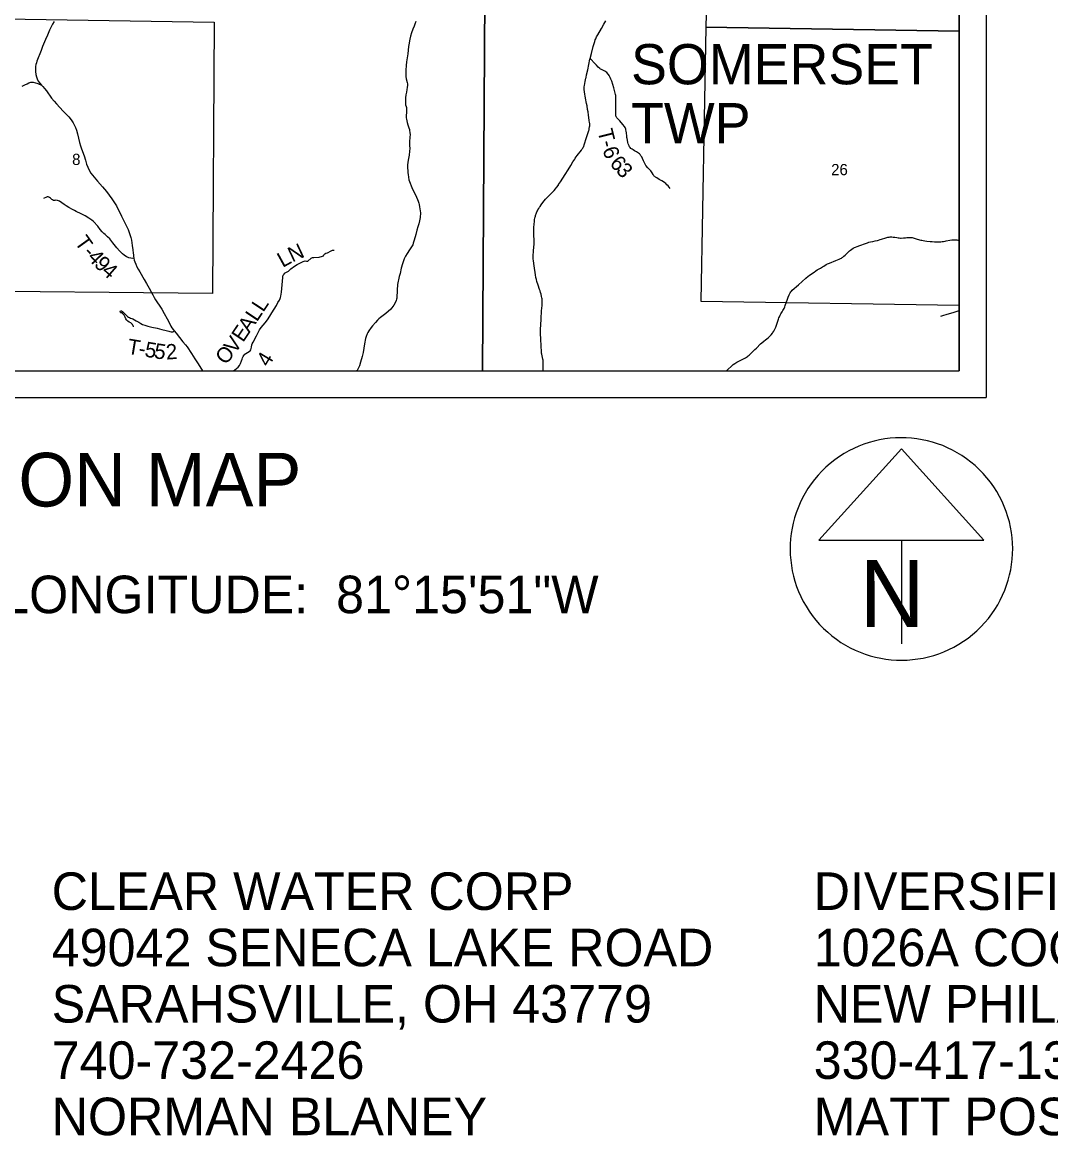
# Model space of a CAD drawing. Extents: x 0 to 34, y 0 to 22.
# Drawn here: x 5.408 to 9.241, y 11.247 to 15.399 of the extents above; entities that cross this region are included whole.
import ezdxf

# ---------------------------------------------------------------- set-up
doc = ezdxf.new("R2010")
doc.units = 0
for name, color, linetype in [('GM_X_Corporation', 7, 'Continuous'), ('GM_X_County_Road', 7, 'Continuous'), ('GM_X_Section_Text', 7, 'Continuous'), ('GM_X_State_Route', 7, 'Continuous'), ('GM_X_Township_Road', 7, 'Continuous'), ('GM_X_Township_Road_Text', 7, 'Continuous'), ('GM_X_Township_Text', 7, 'Continuous'), ('SH_Data', 7, 'Continuous'), ('SH_Text', 7, 'Continuous')]:
    doc.layers.add(name, color=color, linetype=linetype)

msp = doc.modelspace()

# ---------------------------------------------------------------- linework, layer by layer
at = {"layer": 'GM_X_Corporation'}
for points in [[(7.1227, 14.1), (8.9, 14.1), (8.9, 20.9), (7.231, 20.9), (7.2244, 20.2649), (7.1982, 19.2496), (7.1981, 19.2461), (7.1974, 19.2018), (7.1957, 19.0991), (7.1992, 18.9556), (7.197, 18.9465), (7.1949, 18.8464), (7.1846, 18.5133), (7.1817, 18.3306), (7.1804, 18.2238), (7.1572, 17.4131), (7.1504, 16.6562), (7.1434, 16.3848), (7.1318, 15.4937)], [(8.9, 15.3661), (8.9, 16.3711), (7.9815, 16.3875), (7.9552, 15.3809)], [(5.1041, 15.416), (6.1226, 15.3998), (6.117, 14.3875), (5.088, 14.3982)], [(8.9, 14.345), (8.9, 15.3661), (7.9552, 15.3809), (7.9363, 14.3597)]]:
    msp.add_lwpolyline(points, close=True, dxfattribs=at)
at = {"layer": 'GM_X_County_Road'}
for points in [[(5.5268, 15.402), (5.5206, 15.3924), (5.5162, 15.3845), (5.5087, 15.3693), (5.501, 15.3514), (5.4945, 15.3351), (5.4832, 15.3087), (5.4773, 15.2938), (5.4622, 15.254), (5.46, 15.2477), (5.4585, 15.2414), (5.4574, 15.2347), (5.4569, 15.2264), (5.4568, 15.2163), (5.4583, 15.2048), (5.4604, 15.1954), (5.4633, 15.1885), (5.4673, 15.1802), (5.4732, 15.1721), (5.4797, 15.1642)], [(5.4797, 15.1642), (5.4838, 15.1596), (5.4903, 15.1523), (5.4975, 15.1435), (5.5169, 15.1169), (5.5259, 15.1052), (5.5355, 15.0947), (5.5603, 15.0677), (5.5809, 15.0463), (5.5897, 15.0357), (5.5972, 15.0239), (5.6007, 15.0169), (5.6059, 15.0065), (5.6094, 14.9976), (5.6139, 14.9834), (5.6176, 14.9676), (5.6213, 14.9515), (5.6251, 14.9387), (5.6288, 14.9274), (5.6385, 14.9011), (5.643, 14.8854), (5.6469, 14.8708), (5.6513, 14.8594), (5.6574, 14.8476), (5.6636, 14.837), (5.669, 14.8293), (5.6882, 14.8064), (5.7064, 14.7855), (5.7216, 14.7682), (5.7312, 14.7551), (5.7414, 14.7406), (5.7535, 14.7229), (5.7582, 14.7148), (5.7641, 14.7037), (5.7723, 14.6876), (5.7771, 14.6762), (5.796, 14.6391), (5.8016, 14.627), (5.8045, 14.6197), (5.8087, 14.6074), (5.8117, 14.5967), (5.8141, 14.5871), (5.8174, 14.5673), (5.8197, 14.5504), (5.821, 14.538), (5.8218, 14.5316), (5.8223, 14.5274), (5.8232, 14.5197), (5.8246, 14.5125), (5.8265, 14.5061), (5.8302, 14.4968), (5.8347, 14.4877), (5.8398, 14.4783), (5.8453, 14.4685), (5.8618, 14.4398), (5.8703, 14.425), (5.8805, 14.408), (5.8885, 14.3942), (5.8943, 14.383), (5.8995, 14.3728), (5.9047, 14.3644), (5.9094, 14.357), (5.9197, 14.3413), (5.9275, 14.3291), (5.9361, 14.3132), (5.9472, 14.293), (5.9583, 14.2718), (5.9613, 14.2664), (5.9655, 14.26), (5.9699, 14.2538), (5.974, 14.2484), (5.9811, 14.2394), (5.9939, 14.2235), (6.0065, 14.2081), (6.0161, 14.1968), (6.0223, 14.1885), (6.038, 14.1646), (6.0512, 14.1441), (6.0631, 14.1254), (6.0798, 14.1)]]:
    msp.add_lwpolyline(points, dxfattribs=at)
at = {"layer": 'GM_X_State_Route'}
msp.add_lwpolyline([(7.3496, 14.1), (7.3491, 14.1043), (7.3488, 14.1094), (7.3487, 14.1117), (7.3494, 14.1306), (7.3492, 14.1357), (7.3488, 14.1398), (7.3482, 14.1433), (7.3442, 14.1611), (7.3434, 14.166), (7.343, 14.1697), (7.3415, 14.1936), (7.3403, 14.2158), (7.3393, 14.2397), (7.3394, 14.2562), (7.3399, 14.2704), (7.3414, 14.2938), (7.3433, 14.3236), (7.3452, 14.3437), (7.3457, 14.3519), (7.3458, 14.3563), (7.3456, 14.3635), (7.3451, 14.3677), (7.3444, 14.372), (7.3433, 14.3763), (7.3415, 14.3849), (7.3397, 14.3922), (7.3378, 14.3984), (7.3361, 14.4034), (7.3306, 14.4193), (7.3259, 14.4323), (7.3238, 14.4396), (7.3217, 14.4482), (7.3202, 14.4572), (7.3155, 14.4908), (7.3131, 14.5093), (7.3121, 14.5174), (7.3115, 14.5253), (7.3128, 14.5481), (7.3153, 14.5716), (7.3158, 14.5797), (7.3157, 14.5886), (7.3148, 14.604), (7.3145, 14.6136), (7.3149, 14.6337), (7.3156, 14.6464), (7.3164, 14.6569), (7.3172, 14.6632), (7.3184, 14.6695), (7.3191, 14.6724), (7.32, 14.6758), (7.3211, 14.6793), (7.3243, 14.6881), (7.3259, 14.6921), (7.328, 14.6965), (7.3297, 14.6998), (7.3326, 14.705), (7.3357, 14.7096), (7.3379, 14.7127), (7.3422, 14.7188), (7.3482, 14.7269), (7.358, 14.7391), (7.3637, 14.7453), (7.3853, 14.7674), (7.3896, 14.7721), (7.3951, 14.7786), (7.3988, 14.7832), (7.4057, 14.7924), (7.4066, 14.7938), (7.4137, 14.8042), (7.4314, 14.8316), (7.4422, 14.8492), (7.4521, 14.8655), (7.4599, 14.8784), (7.4669, 14.8893), (7.469, 14.8924), (7.4764, 14.9028), (7.4916, 14.9226), (7.4948, 14.927), (7.4968, 14.9301), (7.4986, 14.9333), (7.5002, 14.9365), (7.5023, 14.9421), (7.511, 14.9698), (7.519, 14.9952), (7.52, 14.9987), (7.5209, 15.0026), (7.5221, 15.0095), (7.5225, 15.0132), (7.5227, 15.0178), (7.5226, 15.0223), (7.5224, 15.0247), (7.521, 15.0347), (7.5184, 15.0525), (7.5164, 15.0652), (7.515, 15.0745), (7.5129, 15.0872), (7.511, 15.0968), (7.5071, 15.1166), (7.5057, 15.1249), (7.5047, 15.1302), (7.5029, 15.1415), (7.5023, 15.1475), (7.5022, 15.1531), (7.5025, 15.1588), (7.503, 15.163), (7.506, 15.1787), (7.5084, 15.1905), (7.5091, 15.1939), (7.511, 15.2028), (7.5153, 15.2225), (7.5236, 15.2612), (7.5243, 15.2644), (7.5287, 15.2829), (7.5358, 15.3091), (7.539, 15.3202), (7.5414, 15.328), (7.5435, 15.3337), (7.5452, 15.3378), (7.5485, 15.3448), (7.5526, 15.3526), (7.566, 15.3765), (7.5751, 15.392), (7.5828, 15.4043)], dxfattribs=at)
at = {"layer": 'GM_X_Township_Road'}
for points in [[(6.8744, 15.4024), (6.8712, 15.3925), (6.8684, 15.3854), (6.8635, 15.3737), (6.8585, 15.3599), (6.8547, 15.3476), (6.852, 15.3362), (6.8508, 15.3296), (6.8493, 15.3209), (6.8475, 15.3093), (6.8442, 15.2819), (6.8418, 15.2668), (6.8398, 15.2517), (6.8387, 15.2378), (6.8376, 15.2208), (6.8371, 15.2117), (6.8368, 15.2044), (6.8369, 15.1976), (6.8382, 15.1881), (6.8416, 15.1747), (6.843, 15.1692), (6.8432, 15.1643), (6.8424, 15.1564), (6.8411, 15.1487), (6.8393, 15.1384), (6.8376, 15.1285), (6.8363, 15.1173), (6.8356, 15.1097), (6.8355, 15.1053), (6.836, 15.0977), (6.8366, 15.0916), (6.8382, 15.0854), (6.8391, 15.081), (6.8396, 15.0769), (6.8398, 15.0711), (6.8398, 15.0655), (6.8382, 15.0488), (6.8386, 15.0426), (6.8392, 15.0382), (6.8404, 15.0324), (6.8424, 15.0255), (6.8451, 15.0171), (6.8489, 15.0052), (6.8505, 14.9999), (6.8515, 14.9952), (6.8525, 14.9877), (6.8528, 14.979), (6.8525, 14.9723), (6.8516, 14.9669), (6.8504, 14.9566), (6.8505, 14.9477), (6.8512, 14.9397), (6.8518, 14.9283), (6.8514, 14.9188), (6.8498, 14.9038), (6.8459, 14.8852), (6.8442, 14.8764), (6.8433, 14.8681), (6.8438, 14.8562), (6.8448, 14.8455), (6.8453, 14.8384), (6.8459, 14.8317), (6.8473, 14.8218), (6.8488, 14.8121), (6.8504, 14.8058), (6.8529, 14.7993), (6.8568, 14.7898), (6.8625, 14.7773), (6.8744, 14.7529), (6.883, 14.7323), (6.8853, 14.7253), (6.8865, 14.7192), (6.8877, 14.7111), (6.8914, 14.6883), (6.8905, 14.6719), (6.8886, 14.6592), (6.8853, 14.6471), (6.8815, 14.6362), (6.8786, 14.6239), (6.8745, 14.6082), (6.8689, 14.5874), (6.8649, 14.5752), (6.8629, 14.5698), (6.8588, 14.5623), (6.8509, 14.5509), (6.8418, 14.537), (6.8357, 14.5266), (6.8314, 14.5174), (6.8243, 14.4981), (6.8202, 14.4827), (6.8155, 14.4629), (6.812, 14.4513), (6.8064, 14.422), (6.8049, 14.3998), (6.8044, 14.3931), (6.8043, 14.3793), (6.8035, 14.3707), (6.8028, 14.367), (6.8013, 14.3619), (6.7974, 14.3528), (6.7921, 14.3438), (6.7816, 14.3297), (6.7622, 14.3133), (6.7433, 14.2989), (6.7368, 14.293), (6.7322, 14.2882), (6.7243, 14.2798), (6.7135, 14.2678), (6.7079, 14.2608), (6.6995, 14.249), (6.6956, 14.2427), (6.6926, 14.237), (6.6892, 14.2279), (6.6869, 14.2201), (6.6831, 14.1997), (6.6777, 14.1683), (6.6747, 14.1531), (6.6685, 14.1314), (6.6644, 14.1179), (6.6614, 14.1104), (6.6587, 14.1058), (6.6555, 14.1012), (6.6539, 14.1)], [(7.8225, 14.7799), (7.8147, 14.7892), (7.8105, 14.7936), (7.8063, 14.7975), (7.8027, 14.8004), (7.7973, 14.8043), (7.7921, 14.8075), (7.7819, 14.8132), (7.7724, 14.8189), (7.7679, 14.8218), (7.7651, 14.8237), (7.7633, 14.8253), (7.7617, 14.8271), (7.7607, 14.8288), (7.7596, 14.8314), (7.756, 14.8375), (7.7534, 14.8412), (7.7502, 14.8452), (7.7467, 14.8491), (7.7429, 14.8528), (7.7394, 14.8564), (7.732, 14.8652), (7.7301, 14.8682), (7.7288, 14.8706), (7.7253, 14.8774), (7.7227, 14.8832), (7.7192, 14.8917), (7.7165, 14.8975), (7.7136, 14.9018), (7.7104, 14.906), (7.7081, 14.9086), (7.705, 14.9112), (7.7012, 14.9138), (7.6966, 14.9165), (7.6893, 14.9204), (7.6846, 14.9231), (7.6805, 14.9257), (7.6765, 14.9287), (7.6732, 14.9319), (7.671, 14.9352), (7.6693, 14.9383), (7.668, 14.9412), (7.6669, 14.9439), (7.6661, 14.9465), (7.6651, 14.9504), (7.663, 14.9603), (7.662, 14.966), (7.6615, 14.9692), (7.661, 14.974), (7.6597, 14.9871), (7.6588, 14.9935), (7.6578, 14.9981), (7.6571, 15.0008), (7.6561, 15.0039), (7.6547, 15.0069), (7.6521, 15.0107), (7.6455, 15.0186), (7.6344, 15.0313), (7.6241, 15.0435), (7.6222, 15.046), (7.6211, 15.048), (7.6204, 15.0496), (7.6199, 15.0517), (7.6198, 15.0544), (7.6197, 15.0573), (7.6198, 15.1048), (7.6196, 15.119), (7.6194, 15.1263), (7.6188, 15.1303), (7.6177, 15.135), (7.6127, 15.1549), (7.6091, 15.1672), (7.6046, 15.1796), (7.6013, 15.1874), (7.5986, 15.1932), (7.5947, 15.2006), (7.5925, 15.2043), (7.5909, 15.2064), (7.5864, 15.2115), (7.5827, 15.2147), (7.5796, 15.2169), (7.5739, 15.2199), (7.5668, 15.2229), (7.563, 15.225), (7.5598, 15.2271), (7.5545, 15.2318), (7.5474, 15.239), (7.5424, 15.2444), (7.5243, 15.2644)], [(5.4075, 15.1611), (5.4173, 15.1656), (5.4255, 15.1701), (5.4316, 15.1732), (5.4356, 15.1749), (5.44, 15.1758), (5.4438, 15.176), (5.4484, 15.1754), (5.457, 15.1738), (5.4616, 15.1725), (5.4659, 15.1709), (5.4797, 15.1642)], [(5.8232, 14.5197), (5.8173, 14.5188), (5.8118, 14.5192), (5.8049, 14.5209), (5.8002, 14.5228), (5.7962, 14.5248), (5.7869, 14.5307), (5.7811, 14.5357), (5.7759, 14.5407), (5.7702, 14.5465), (5.7595, 14.5585), (5.7451, 14.5764), (5.7338, 14.5913), (5.7253, 14.5997), (5.7197, 14.6044), (5.716, 14.6074), (5.7117, 14.6113), (5.7091, 14.6139), (5.7051, 14.6184), (5.6983, 14.6267), (5.6887, 14.6387), (5.6734, 14.6559), (5.6667, 14.6619), (5.6632, 14.6644), (5.6554, 14.6691), (5.6423, 14.6771), (5.6276, 14.685), (5.6089, 14.6942), (5.6022, 14.6973), (5.5951, 14.7013), (5.5815, 14.7085), (5.5712, 14.7145), (5.5639, 14.7192), (5.5554, 14.7255), (5.5464, 14.7319), (5.5388, 14.7349), (5.533, 14.7357), (5.5283, 14.7348), (5.5238, 14.7353), (5.52, 14.7366), (5.5178, 14.7384), (5.5157, 14.7404), (5.5128, 14.7433), (5.509, 14.7463), (5.5063, 14.7477), (5.5036, 14.7484), (5.5003, 14.7485), (5.4972, 14.7476), (5.486, 14.7421)], [(8.0328, 14.1), (8.0359, 14.1027), (8.053, 14.1187), (8.0578, 14.1227), (8.0641, 14.1273), (8.0709, 14.1315), (8.088, 14.1404), (8.0988, 14.1458), (8.1034, 14.1481), (8.1067, 14.15), (8.1109, 14.1528), (8.1136, 14.155), (8.1171, 14.1579), (8.1211, 14.162), (8.1255, 14.1666), (8.1303, 14.1714), (8.1384, 14.1785), (8.1446, 14.1844), (8.1598, 14.2003), (8.1637, 14.2041), (8.1712, 14.2105), (8.1779, 14.2155), (8.1833, 14.2191), (8.1893, 14.2238), (8.1943, 14.2283), (8.1996, 14.2343), (8.2037, 14.2395), (8.2056, 14.2422), (8.2088, 14.247), (8.2105, 14.2498), (8.2133, 14.2552), (8.2161, 14.262), (8.219, 14.2696), (8.2213, 14.2773), (8.2235, 14.2848), (8.2246, 14.2886), (8.2258, 14.2925), (8.2274, 14.2966), (8.2295, 14.3012), (8.2328, 14.3077), (8.2354, 14.3124), (8.2399, 14.3194), (8.2427, 14.324), (8.2469, 14.332), (8.2499, 14.3386), (8.2515, 14.3427), (8.2596, 14.3665), (8.2627, 14.3748), (8.2663, 14.383), (8.2704, 14.391), (8.2722, 14.3938), (8.2747, 14.3971), (8.2771, 14.3998), (8.3005, 14.4203), (8.3282, 14.445), (8.3367, 14.4522), (8.3406, 14.4551), (8.3491, 14.4613), (8.3589, 14.4679), (8.3654, 14.4721), (8.3711, 14.4756), (8.3834, 14.4827), (8.3907, 14.487), (8.3949, 14.4896), (8.4038, 14.4955), (8.4064, 14.4971), (8.4092, 14.4983), (8.4162, 14.5015), (8.4403, 14.5108), (8.4462, 14.5134), (8.453, 14.5162), (8.4576, 14.5183), (8.4606, 14.5199), (8.4634, 14.5217), (8.4664, 14.5236), (8.4703, 14.5268), (8.4749, 14.5308), (8.4818, 14.5384), (8.4863, 14.5426), (8.4909, 14.5468), (8.4947, 14.5498), (8.5003, 14.5537), (8.5047, 14.5564), (8.5096, 14.5591), (8.5128, 14.5607), (8.5199, 14.5636), (8.5299, 14.5673), (8.5504, 14.5746), (8.5586, 14.5774), (8.5632, 14.5788), (8.5692, 14.5803), (8.5786, 14.5823), (8.5873, 14.5842), (8.5952, 14.5861), (8.599, 14.5871), (8.6058, 14.5891), (8.6098, 14.5904), (8.6267, 14.5958), (8.6304, 14.5969), (8.6343, 14.5977), (8.6383, 14.5984), (8.6429, 14.5988), (8.6486, 14.5989), (8.6542, 14.5985), (8.6598, 14.5978), (8.6674, 14.5965), (8.6722, 14.5958), (8.6767, 14.5952), (8.6808, 14.5948), (8.6841, 14.5947), (8.6921, 14.5949), (8.7, 14.596), (8.7053, 14.5967), (8.7086, 14.5971), (8.7122, 14.5973), (8.7163, 14.5971), (8.72, 14.5969), (8.7241, 14.5964), (8.7282, 14.5955), (8.7396, 14.5921), (8.7521, 14.5884), (8.7565, 14.5874), (8.7601, 14.5867), (8.7659, 14.5856), (8.7722, 14.5846), (8.7799, 14.5836), (8.7914, 14.5824), (8.7988, 14.5817), (8.8075, 14.581), (8.814, 14.5808), (8.8226, 14.5806), (8.8276, 14.5807), (8.8314, 14.5809), (8.8367, 14.5815), (8.8412, 14.582), (8.8472, 14.583), (8.8515, 14.5839), (8.8653, 14.5868), (8.8724, 14.588), (8.8757, 14.5883), (8.8792, 14.5886), (8.8882, 14.5882), (8.8909, 14.5878), (8.8944, 14.5871), (8.8974, 14.5863), (8.9, 14.5855)], [(6.2804, 14.2306), (6.2888, 14.2469), (6.2919, 14.2519), (6.2985, 14.2607), (6.3123, 14.2784), (6.3214, 14.2897), (6.3303, 14.3031), (6.3378, 14.3158), (6.3549, 14.3437), (6.3606, 14.3538), (6.3659, 14.3635), (6.3688, 14.3696), (6.3703, 14.3736), (6.3714, 14.3777), (6.3731, 14.385), (6.3739, 14.3923), (6.3748, 14.4068), (6.3779, 14.4339), (6.3785, 14.4479), (6.3791, 14.4521), (6.3804, 14.4563), (6.3831, 14.4606), (6.3854, 14.4632), (6.3928, 14.4679), (6.3994, 14.4715), (6.4019, 14.4739), (6.408, 14.4799), (6.4221, 14.4898), (6.4326, 14.4963), (6.4442, 14.5027), (6.454, 14.5075), (6.4584, 14.5091), (6.4623, 14.5099), (6.4668, 14.5091), (6.4715, 14.5087), (6.484, 14.5197), (6.4891, 14.5216), (6.4944, 14.5224), (6.5142, 14.5239), (6.5269, 14.5267), (6.5306, 14.5289), (6.5321, 14.5323), (6.5353, 14.5358), (6.5387, 14.538), (6.5448, 14.5401), (6.5587, 14.5472), (6.5644, 14.549), (6.5698, 14.5493)], [(5.8222, 14.2633), (5.8215, 14.2662), (5.8201, 14.2692), (5.8179, 14.2728), (5.8157, 14.2752), (5.8116, 14.2781), (5.8059, 14.2816), (5.8009, 14.2848), (5.7976, 14.2872), (5.7954, 14.2899), (5.7936, 14.2931), (5.7907, 14.2995), (5.7867, 14.3071), (5.7835, 14.3112), (5.7807, 14.3139), (5.7774, 14.3158), (5.775, 14.3162), (5.7731, 14.3171), (5.772, 14.319), (5.7718, 14.3209), (5.7735, 14.3227), (5.775, 14.3237), (5.7773, 14.3237), (5.7807, 14.3207), (5.79, 14.3123), (5.7955, 14.3059), (5.7997, 14.3023), (5.8036, 14.2995), (5.8068, 14.2979), (5.8103, 14.2965), (5.8154, 14.2951), (5.8198, 14.2935), (5.8318, 14.2866), (5.8421, 14.2804), (5.8492, 14.2762), (5.8561, 14.2727), (5.8648, 14.2693), (5.8761, 14.2661), (5.8904, 14.2629), (5.9108, 14.2587), (5.9281, 14.2541), (5.9436, 14.2501), (5.9538, 14.247), (5.9581, 14.2459), (5.9629, 14.2445), (5.9667, 14.2444), (5.9697, 14.2455), (5.974, 14.2484)], [(8.8311, 14.3035), (8.8348, 14.3044), (8.8384, 14.3054), (8.8546, 14.3103), (8.8772, 14.3172), (8.8993, 14.324), (8.9, 14.3242)], [(6.1944, 14.1), (6.1992, 14.1032), (6.2128, 14.1135), (6.2171, 14.1189), (6.2215, 14.1267), (6.2251, 14.1374), (6.227, 14.1436), (6.2285, 14.1478), (6.2304, 14.1528), (6.2331, 14.1573), (6.2374, 14.1615), (6.2414, 14.1647), (6.2476, 14.168), (6.2537, 14.1717), (6.2564, 14.1743), (6.2591, 14.1778), (6.2609, 14.1826), (6.2618, 14.1884), (6.2632, 14.1965), (6.2644, 14.1999), (6.2678, 14.2062), (6.2804, 14.2306)]]:
    msp.add_lwpolyline(points, dxfattribs=at)
at = {"layer": 'GM_X_Township_Text'}
for points in [[(7.1227, 14.1), (8.9, 14.1), (8.9, 19.2243), (7.7835, 19.2432), (7.6914, 19.2442), (7.3421, 19.2478), (7.2323, 19.2489), (7.1982, 19.2496)], [(2.6249, 19.1744), (2.6223, 19.0497), (2.622, 19.0358), (2.6202, 18.9481), (2.604, 17.9706), (2.6039, 17.9669), (2.5791, 16.4754), (2.4938, 16.4762), (2.1, 16.4804), (2.1, 14.1), (7.1227, 14.1)], [(7.1227, 14.1), (7.1318, 15.4937), (7.1434, 16.3848), (7.1504, 16.6562), (7.1572, 17.4131), (7.1804, 18.2238), (7.1817, 18.3306), (7.1846, 18.5133), (7.1949, 18.8464), (7.197, 18.9465), (7.1992, 18.9556), (7.1957, 19.0991), (7.1536, 19.0995)]]:
    msp.add_lwpolyline(points, dxfattribs=at)
at = {"layer": 'SH_Data'}
for p, q in [((9, 21), (9, 14)), ((8.9, 20.9), (8.9, 14.1)), ((2.1, 14.1), (8.9, 14.1)), ((2, 14), (9, 14)), ((8.6845, 13.809), (8.3769, 13.4678)), ((8.9921, 13.4678), (8.6845, 13.809)), ((8.3769, 13.4678), (8.9921, 13.4678)), ((8.6845, 13.4678), (8.6845, 13.081)), ((8.6845, 13.4353), (8.6845, 13.4353)), ((8.6845, 13.4353), (8.6845, 13.4353))]:
    msp.add_line(p, q, dxfattribs=at)
msp.add_arc((8.6845, 13.4353), 0.4148, 129.7798, 129.7633, dxfattribs=at)

# ---------------------------------------------------------------- texts
at = {"layer": 'GM_X_Section_Text'}
for s, height, p in [('8', 0.0419, (5.5933, 14.867)), ('26', 0.04186, (8.4226, 14.829))]:
    msp.add_text(s, height=height, rotation=0, dxfattribs=at).set_placement(p)
at = {"layer": 'GM_X_Township_Road_Text'}
for s, rotation, p in [('T', 283.9411, (7.5514, 14.9944)), ('-', 284.5926, (7.5618, 14.9525)), ('6', 289.5294, (7.5693, 14.9248)), ('6', 313.1419, (7.5942, 14.8701)), ('3', 311.6513, (7.6178, 14.8449)), ('T', 305.6338, (5.6005, 14.5784)), ('N', 25.1883, (6.4143, 14.503)), ('-', 314.0172, (5.631, 14.5369)), ('4', 313.6016, (5.6472, 14.5202)), ('L', 28.8157, (6.3779, 14.483)), ('9', 314.6147, (5.6721, 14.494)), ('4', 318.7621, (5.6999, 14.4661)), ('L', 56.5615, (6.3057, 14.3156)), ('A', 56.2486, (6.2542, 14.2384)), ('L', 56.2596, (6.282, 14.28)), ('E', 56.2393, (6.2305, 14.2031)), ('T', 350.5419, (5.7963, 14.1639)), ('5', 350.6632, (5.8613, 14.153)), ('5', 351.0876, (5.8963, 14.1473)), ('2', 3.9925, (5.9448, 14.1413)), ('V', 54.1549, (6.2, 14.1607)), ('-', 350.5551, (5.8382, 14.1569)), ('O', 50.1389, (6.1653, 14.1189)), ('4', 59.1997, (6.3255, 14.1111))]:
    msp.add_text(s, height=0.0568, rotation=rotation, dxfattribs=at).set_placement(p)
at = {"layer": 'GM_X_Township_Text'}
for s, p in [('SOMERSET', (7.6766, 15.168)), ('TWP', (7.6766, 14.948))]:
    msp.add_text(s, height=0.15, rotation=0, dxfattribs=at).set_placement(p)
at = {"layer": 'SH_Data'}
msp.add_text('N', height=0.25, dxfattribs=at).set_placement((8.5292, 13.1439))
at = {"layer": 'SH_Text'}
for s, height, p in [('LOCATION MAP', 0.2, (4.4269, 13.5937)), ('LATITUDE:  39°55\'14"N     LONGITUDE:  81°15\'51"W', 0.14, (3.071, 13.1958)), ('CLEAR WATER CORP', 0.14, (5.5172, 12.0892)), ('DIVERSIFIED GAS & OIL PLC', 0.14, (8.3576, 12.0892)), ('49042 SENECA LAKE ROAD', 0.14, (5.5172, 11.8792)), ('1026A COOKSON AVENUE SE', 0.14, (8.3576, 11.8792)), ('SARAHSVILLE, OH 43779', 0.14, (5.5172, 11.6692)), ('NEW PHILADELPHIA, OH 44663', 0.14, (8.3576, 11.6692)), ('740-732-2426', 0.14, (5.5172, 11.4592)), ('330-417-1397', 0.14, (8.3576, 11.4592)), ('NORMAN BLANEY    ', 0.14, (5.5172, 11.2492)), ('MATT POSTLETHWAIT    ', 0.14, (8.3576, 11.2492))]:
    msp.add_text(s, height=height, dxfattribs=at).set_placement(p)

doc.saveas('drawing.dxf')
